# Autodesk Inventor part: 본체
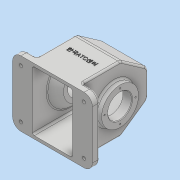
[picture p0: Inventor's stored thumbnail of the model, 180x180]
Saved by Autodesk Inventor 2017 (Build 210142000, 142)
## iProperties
Part Number: 본체
Material: 일반
Document SubType Name: Modeling
Designer: MRC
Density: 1 g/cm^3
Appearance: 기본값
Author: MRC
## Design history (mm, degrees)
sketch "스케치4"
  geometry: L1 (38.5, -55)-(-38.5, -55); L2 (-38.5, -55)-(-38.5, 55); L3 (-38.5, 55)-(38.5, 55); L4 (38.5, 55)-(38.5, -55); L5 (38.5, -55)-(-38.5, 55); L6 (-38.5, -55)-(38.5, 55); 1 further point
  constraints: 12 end point, 2 midpoint, 2 parallel, 1 horizontal, 1 perpendicular
  dimensions: "d12" = 110 distance of L3.end L1.start; "d13" = 77 distance of L1.start L1.end
extrude "돌출4" new body sketch "스케치4" distance "d14" = 122; taper "d15" = 0 deg
sketch "스케치5"
  geometry: L1 (0, 77)-(31.509, 122); L2 (0, 0)-(0, 122) reference; L3 (110, 0)-(0, 0) reference; L4 (0, 122)-(110, 122) reference; 1 further point
  constraints: 2 end point, 2 point on line
  dimensions: "d16" = 35 deg angle of L1 L2; "d17" = 77 distance from line of L3 L1.start
extrude "돌출5" cut sketch "스케치5" distance "d18" = 122; taper "d19" = 0 deg
feature "쉘1" dims "d20" = 5
sketch "스케치7"
  geometry: L1 (-38.5, 55)-(-38.5, -55) reference; L2 (38.5, 55)-(-38.5, 55) reference; L3 (-38.5, 55)-(-67, 55); L4 (-67, 55)-(-67, -55); L5 (-38.5, -55)-(38.5, -55) reference; L6 (-67, -55)-(-38.5, -55); 1 further point
  constraints: 6 end point, 2 perpendicular, 1 horizontal
  dimensions: "d25" = 67 distance from line of L4 point (0, 0)
extrude "돌출7" join sketch "스케치7" distance "d26" = 12; taper "d27" = 0 deg
node "작업 평면1"
sketch "스케치8"
  geometry: L1 (-26.509, -122)-(73.491, -122) reference; C1 r 37.5 at (23.491, -57); 1 further point
  constraints: 1 centre point, 1 vertical alignment
  dimensions: "d29" = 75 diameter of C1; "d30" = 65 distance from line of L1 C1.centre
extrude "돌출8" join sketch "스케치8" stored distance "d31" = 12; taper "d32" = 0 deg
sketch "스케치9"
  geometry: L1 (-55, -65)-(55, -65) reference; C1 r 37.5 at (0, 0) reference; 3 further points
  constraints: 1 midpoint, 1 vertical alignment
  dimensions: "d33" = 29 distance of C1.centre point (0, 29)
hole "구멍1" sketch "스케치9" at (0, 29) diameter "d34" = 2.459; stored, may be unused: countersink angle "d38" = 90 deg, drill point angle "d40" = 118 deg; dims "d35" = 6, "d36" = 4, "d37" = 2, "d39" = 8
node "작업 평면2"
sketch "스케치10"
  geometry: L1 (78.491, -122)-(-31.509, -122) reference; C1 r 31 at (23.491, -57); 2 further points
  constraints: 1 centre point, 1 midpoint, 1 vertical alignment
  dimensions: "d45" = 62 diameter of C1; "d46" = 65 distance from line of C1.centre L1
extrude "돌출9" join sketch "스케치10" distance "d47" = 10; taper "d48" = 0 deg
sketch "스케치11"
  geometry: C1 r 31 at (0, 0) reference; 2 further points
  constraints: 1 vertical alignment
  dimensions: "d49" = 26 distance of C1.centre point (0, 26)
hole "구멍2" sketch "스케치11" at (0, 26) diameter "d50" = 2.459; stored, may be unused: countersink angle "d54" = 90 deg, drill point angle "d56" = 118 deg; dims "d51" = 6, "d52" = 4, "d53" = 2, "d55" = 8
node "작업 평면3"
sketch "스케치13"
  geometry: C1 r 31 at (0, 0) reference; C2 r 27 at (0, 0); 1 further point
  constraints: 1 centre point, 1 coincident
  dimensions: "d63" = 54 diameter of C2
extrude "돌출10" join sketch "스케치13" stored distance "d64" = 10; taper "d65" = 45 deg
hole "구멍3" diameter "d68" = 40; stored, may be unused: countersink angle "d72" = 90 deg, drill point angle "d74" = 118 deg; dims "d66" = 10, "d67" = 10, "d69" = 6, "d70" = 4, "d71" = 2, "d73" = 8
fillet "모깎기1" dims "d75" = 14
sketch "스케치14"
  geometry: A1 r 14 centre (-53, 41) between (-53, 55) and (-67, 41) reference; A2 r 14 centre (53, 41) between (67, 41) and (53, 55) reference; A3 r 14 centre (53, -41) between (53, -55) and (67, -41) reference; A4 r 14 centre (-53, -41) between (-67, -41) and (-53, -55) reference; 5 further points
  constraints: 4 coincident
hole "구멍4" sketch "스케치14" at (-53, 41), (53, 41), (53, -41), (-53, -41) diameter "d76" = 5.5; stored, may be unused: countersink angle "d80" = 90 deg, drill point angle "d82" = 118 deg; dims "d77" = 6, "d78" = 15, "d79" = 2, "d81" = 8
node "작업 평면4"
sketch "스케치15"
  geometry: L1 (38.5, -55)-(-38.5, -55) reference; L2 (38.5, -23.491)-(38.5, -55) reference; C1 r 6 at (0, 0); 1 further point
  constraints: 1 centre point
  dimensions: "d87" = 12 diameter of C1; "d88" = 38.5 distance from line of C1.centre L2; "d89" = 55 distance from line of C1.centre L1
extrude "돌출11" join sketch "스케치15" stored distance "d90" = 10; taper "d91" = 0 deg
hole "구멍5" diameter "d94" = 5.188; stored, may be unused: countersink angle "d98" = 90 deg, drill point angle "d100" = 118 deg; dims "d92" = 10, "d93" = 10, "d95" = 12, "d96" = 1, "d97" = 2, "d99" = 16
sketch "스케치16"
  geometry: L1 (-14.5, -77)-(-28.5, -77) reference; L2 (0, -65)-(0, 0) reference; 2 further points
  constraints: 1 other
  dimensions: "d101" = 50 distance from line of L1 point (38.5, -27); "d102" = 38.5 distance from line of point (38.5, -27) L2
feature "엠보싱1" sketch "스케치16" dims "d12" = 110, "d13" = 77, "d103" = 0.5, "d104" = 0
fillet "모깎기2" dims "d105" = 10
fillet "모깎기3" dims "d106" = 3
chamfer "모따기1" distance "d107" = 1; stored, may be unused: second distance "d108" = 2, angle "d109" = 45 deg
node "솔리드2"
mirror "미러2"
mirror "미러3"
pattern_circular "원형 패턴1" dims angle "d42" = 360 deg
pattern_circular "원형 패턴2" dims angle "d58" = 360 deg
other parameters: "d28" = 5, "d62" = -24, "d83" = 126
